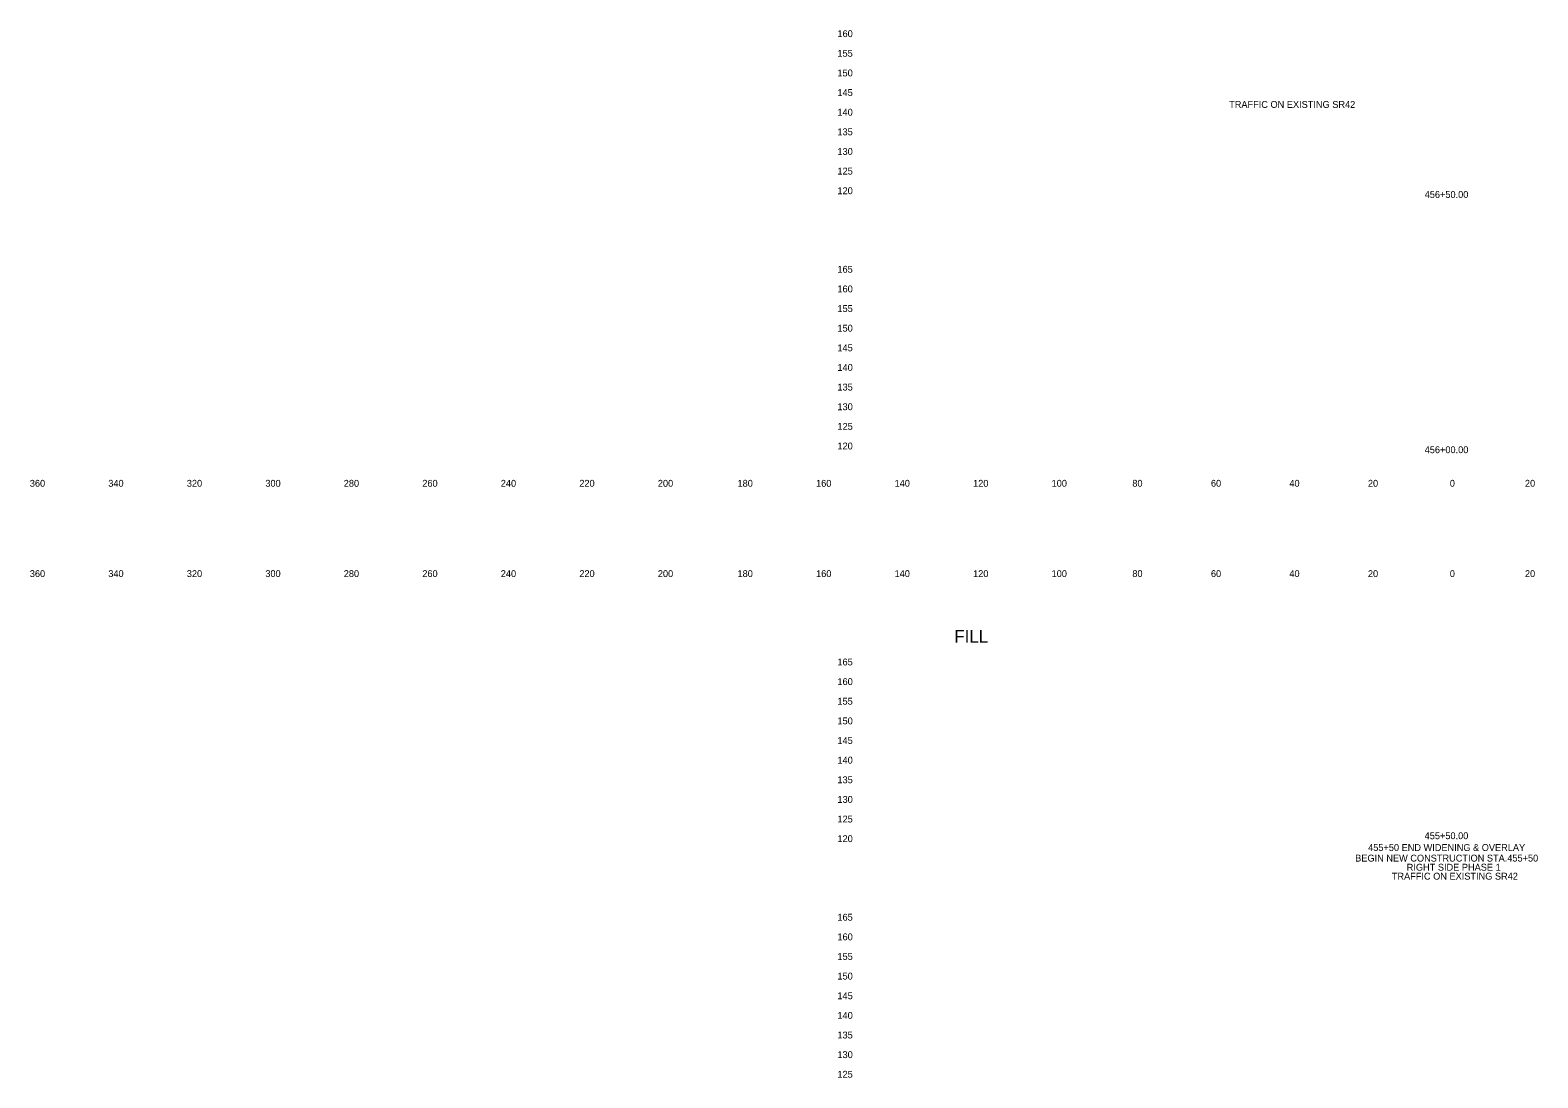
# Model space of a CAD drawing. Extents: x 21281 to 22024, y 6472 to 15198.
# Drawn here: x 21280.5 to 21664.5, y 7014.8 to 7281.6 of the extents above; entities that cross this region are included whole.
import ezdxf

# ---------------------------------------------------------------- set-up
doc = ezdxf.new("R2010")
doc.units = 0
for name, color, linetype in [('XS_SHEET_LABELS_ELEVATION', 7, 'Continuous'), ('XS_SHEET_LABELS_OFFSET', 7, 'Continuous'), ('XS_SHEET_LABELS_STATION', 7, 'Continuous')]:
    doc.layers.add(name, color=color, linetype=linetype)

msp = doc.modelspace()

# ---------------------------------------------------------------- texts
at = {"layer": 'XS_SHEET_LABELS_ELEVATION'}
for s, p in [('  160  ', (21484.84, 7279.84)), ('  155  ', (21484.84, 7274.84)), ('  150  ', (21484.84, 7269.84)), ('  145  ', (21484.84, 7264.84)), ('  140  ', (21484.84, 7259.84)), ('  135  ', (21484.84, 7254.84)), ('  130  ', (21484.84, 7249.84)), ('  125  ', (21484.84, 7244.84)), ('  120  ', (21484.84, 7239.84)), ('  165  ', (21484.84, 7219.84)), ('  160  ', (21484.84, 7214.84)), ('  155  ', (21484.84, 7209.84)), ('  150  ', (21484.84, 7204.84)), ('  145  ', (21484.84, 7199.84)), ('  140  ', (21484.84, 7194.84)), ('  135  ', (21484.84, 7189.84)), ('  130  ', (21484.84, 7184.84)), ('  125  ', (21484.84, 7179.84)), ('  120  ', (21484.84, 7174.84)), ('  165  ', (21484.84, 7119.84)), ('  160  ', (21484.84, 7114.84)), ('  155  ', (21484.84, 7109.84)), ('  150  ', (21484.84, 7104.84)), ('  145  ', (21484.84, 7099.84)), ('  140  ', (21484.84, 7094.84)), ('  135  ', (21484.84, 7089.84)), ('  130  ', (21484.84, 7084.84)), ('  125  ', (21484.84, 7079.84)), ('  120  ', (21484.84, 7074.84)), ('  165  ', (21484.84, 7054.84)), ('  160  ', (21484.84, 7049.84)), ('  155  ', (21484.84, 7044.84)), ('  150  ', (21484.84, 7039.84)), ('  145  ', (21484.84, 7034.84)), ('  140  ', (21484.84, 7029.84)), ('  135  ', (21484.84, 7024.84)), ('  130  ', (21484.84, 7019.84)), ('  125  ', (21484.84, 7014.84))]:
    msp.add_text(s, height=1.75, dxfattribs=at).set_placement(p)
at = {"layer": 'XS_SHEET_LABELS_OFFSET'}
for s, height, p in [('  360  ', 1.75, (21279.14, 7165.34)), ('  340  ', 1.75, (21299.13, 7165.34)), ('  320  ', 1.75, (21319.13, 7165.34)), ('  300  ', 1.75, (21339.13, 7165.34)), ('  280  ', 1.75, (21359.1, 7165.34)), ('  260  ', 1.75, (21379.11, 7165.34)), ('  240  ', 1.75, (21399.1, 7165.34)), ('  220  ', 1.75, (21419.1, 7165.34)), ('  200  ', 1.75, (21439.1, 7165.34)), ('  180  ', 1.75, (21459.39, 7165.34)), ('  160  ', 1.75, (21479.4, 7165.34)), ('  140  ', 1.75, (21499.39, 7165.34)), ('  120  ', 1.75, (21519.39, 7165.34)), ('  100  ', 1.75, (21539.39, 7165.34)), ('  80  ', 1.75, (21559.95, 7165.34)), ('  60  ', 1.75, (21579.97, 7165.34)), ('  40  ', 1.75, (21599.95, 7165.34)), ('  20  ', 1.75, (21619.95, 7165.34)), ('  0  ', 1.75, (21640.81, 7165.34)), ('  0  ', 1.75, (21640.81, 7165.34)), ('  20  ', 1.75, (21659.95, 7165.34)), ('  360  ', 1.75, (21279.14, 7142.34)), ('  340  ', 1.75, (21299.13, 7142.34)), ('  320  ', 1.75, (21319.13, 7142.34)), ('  300  ', 1.75, (21339.13, 7142.34)), ('  280  ', 1.75, (21359.1, 7142.34)), ('  260  ', 1.75, (21379.11, 7142.34)), ('  240  ', 1.75, (21399.1, 7142.34)), ('  220  ', 1.75, (21419.1, 7142.34)), ('  200  ', 1.75, (21439.1, 7142.34)), ('  180  ', 1.75, (21459.39, 7142.34)), ('  160  ', 1.75, (21479.4, 7142.34)), ('  140  ', 1.75, (21499.39, 7142.34)), ('  120  ', 1.75, (21519.39, 7142.34)), ('  100  ', 1.75, (21539.39, 7142.34)), ('  80  ', 1.75, (21559.95, 7142.34)), ('  60  ', 1.75, (21579.97, 7142.34)), ('  40  ', 1.75, (21599.95, 7142.34)), ('  20  ', 1.75, (21619.95, 7142.34)), ('  0  ', 1.75, (21640.81, 7142.34)), ('  0  ', 1.75, (21640.81, 7142.34)), ('  20  ', 1.75, (21659.95, 7142.34)), ('FILL', 3.222, (21515.91, 7125.65))]:
    msp.add_text(s, height=height, dxfattribs=at).set_placement(p)
at = {"layer": 'XS_SHEET_LABELS_STATION'}
for s, p in [('TRAFFIC ON EXISTING SR42', (21585.91, 7261.82)), ('  456+50.00  ', (21634.41, 7238.89)), ('  456+00.00  ', (21634.41, 7173.89)), ('  455+50.00  ', (21634.4, 7075.59)), (' 455+50 END WIDENING & OVERLAY', (21620.66, 7072.59)), ('BEGIN NEW CONSTRUCTION STA.455+50 ', (21618.01, 7069.89)), ('TRAFFIC ON EXISTING SR42', (21627.34, 7065.29)), ('RIGHT SIDE PHASE 1', (21631.14, 7067.57))]:
    msp.add_text(s, height=1.75, dxfattribs=at).set_placement(p)

doc.saveas('drawing.dxf')
